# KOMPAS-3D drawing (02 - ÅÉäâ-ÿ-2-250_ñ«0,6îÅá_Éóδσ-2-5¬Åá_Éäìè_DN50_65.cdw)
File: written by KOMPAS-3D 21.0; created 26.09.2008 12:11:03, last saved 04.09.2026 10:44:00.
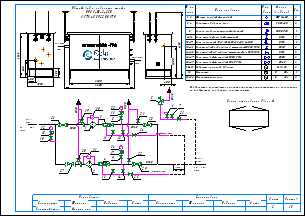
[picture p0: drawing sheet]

Sheets 1-2: A3, landscape

Document properties: Наименование: Макро:21; Автор: RaskoAdmin; Форматы листов документа: 2xA3; Полное имя файла: \\UR38nt01\Departments\КТО\КБ ПУРДГ\Заявки\Прайс-лист на типовые шкафы ГРПШ\ПРДГ_стандарт_20_03_2026\ПРДГ с РДНК\ПРДГ-Ш-2-250_до0,6МПа_Рвых-2-5кПа_РДНК_DN50_65.cdw

Title block, sheet 1: Наименование: Пункт учета газа / ПУГ-Ш-400-Р / ЛГТИ.485922.001ТУ; designation: ЛГТИ.03.4411141; sheet number: 1; Количество листов документа: 2; organisation: ООО "ЭЛЬСТЕР Газэлектроника"; Форматы листов документа: A3; stored path: C:\Рабочие документы\Компас\ПУГ\Схема.cdw; Разработал: Устинов; Проверил: Кошкин; Утвердил: Кошкин
Title block, sheet 2: sheet number: 2; stored path: D:\Рабочие документы\Заявки\ПУРДГ\ПУРДГ-ШУЭО-2-100-Р 4411220.cdw; designation, second copy: ЛГТИ.03.4411141-

Views: Вид 1, Вид 2
Referenced files: wcvoit.frw
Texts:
  Normal
  Вход
  газа
  PDI
  Выход
  Р=     кПа
  DN65
  DN50
  DN20
  Импульс DN15
  ≥5DN
  HYSWLongFangSong
  № на
  схеме
  Усл.
  обозн.
  Марка
  (модель)
  Кол.
  Фильтр газовый фланцевый
  ФГ 16-50
  Регулятор давления газа
  РДНК-50
  Клапан предохранительный сбросной
  КПС DN20
  Кран шаровой газовый латунный
  DN15
  Кран кнопочный VE-РАСКО-НЗ-1,6-G1/2-М20
  Кран шаровой "под приварку" штуцерный DN20 PN16
  Кран шаровой "под приварку" штуцерный п/п DN15 PN16
  Кран шаровой фланцевый DN50 PN16
  Кран шаровой фланцевый DN65 PN16
  Индикатор перепада давления
  Delta 15
  Манометр
  Манометр-напоромер
  0...     МПа
  0...     кПа
  Общий вид и габариты шкафа
  ПРДГ-Ш-2-250
  Выход газа
  Вход газа
  Схема открывания дверей
  Р=        МПа
  logo-rasko-ge.png
  Предприятие изготовитель может заменять комплектующие на аналогичные,
  не ухудшающие заявленных характеристик.
  Должность
  Конструктор
  Фамилия
  Подпись
  Дата
  Согласовано
  Максимкин
  Лист
  Листов
  POLYLINE_STYLE_0.18_RGB_0_0_0
  POLYLINE_STYLE_0.50_RGB_0_0_0
  POLYLINE_STYLE_0.34_RGB_0_0_0
  PHANTOM_RGB_0_0_0_SC_1_THICK_0.18
  K5LT_THIN_RGB_0_0_0_THICK_0.18
  K5LT32769_RGB_0_0_0_THICK_0.18
  K5LT12_RGB_0_0_0_SC_1_THICK_0.18
  K5LT_DASHED_RGB_0_0_0_SC_1_THICK_0.18
  ACISOTGL_RGB_0_0_0_SC_0.8_THICK_0.25
  CONTINUOUS_RGB_0_127_31_THICK_0.3
  CONTINUOUS_RGB_0_0_255_THICK_0.35
  CONTINUOUS_RGB_255_0_0_THICK_0.35
  POLYLINE_STYLE_0.25_RGB_0_0_0
  CONTINUOUS_RGB_0_0_0_THICK_0.5
  POLYLINE_STYLE_0.35_RGB_0_0_255
  CONTINUOUS_RGB_0_0_0_THICK_0.4
  CONTINUOUS_RGB_0_0_0_THICK_0.35
  Без оформления
Dimensions and other numbers on the sheet: 1; 2; 3; 4; 5; 10; 27; 28; 29; 23; 8; 12; 19; 20; 21; 22; 25; 24; 30; 31; 15; 16; 26; 6; 7; 11; 14; 13; 33; 1, 2; 3, 4; 6-14; 9; 15-17; 18-23; 24-25; 26-27; 28-29; 30-31; 32; 33-34; 400; 1050; 500; 305; 1565; 2600; 17; 34; 1000; 4130; 2300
